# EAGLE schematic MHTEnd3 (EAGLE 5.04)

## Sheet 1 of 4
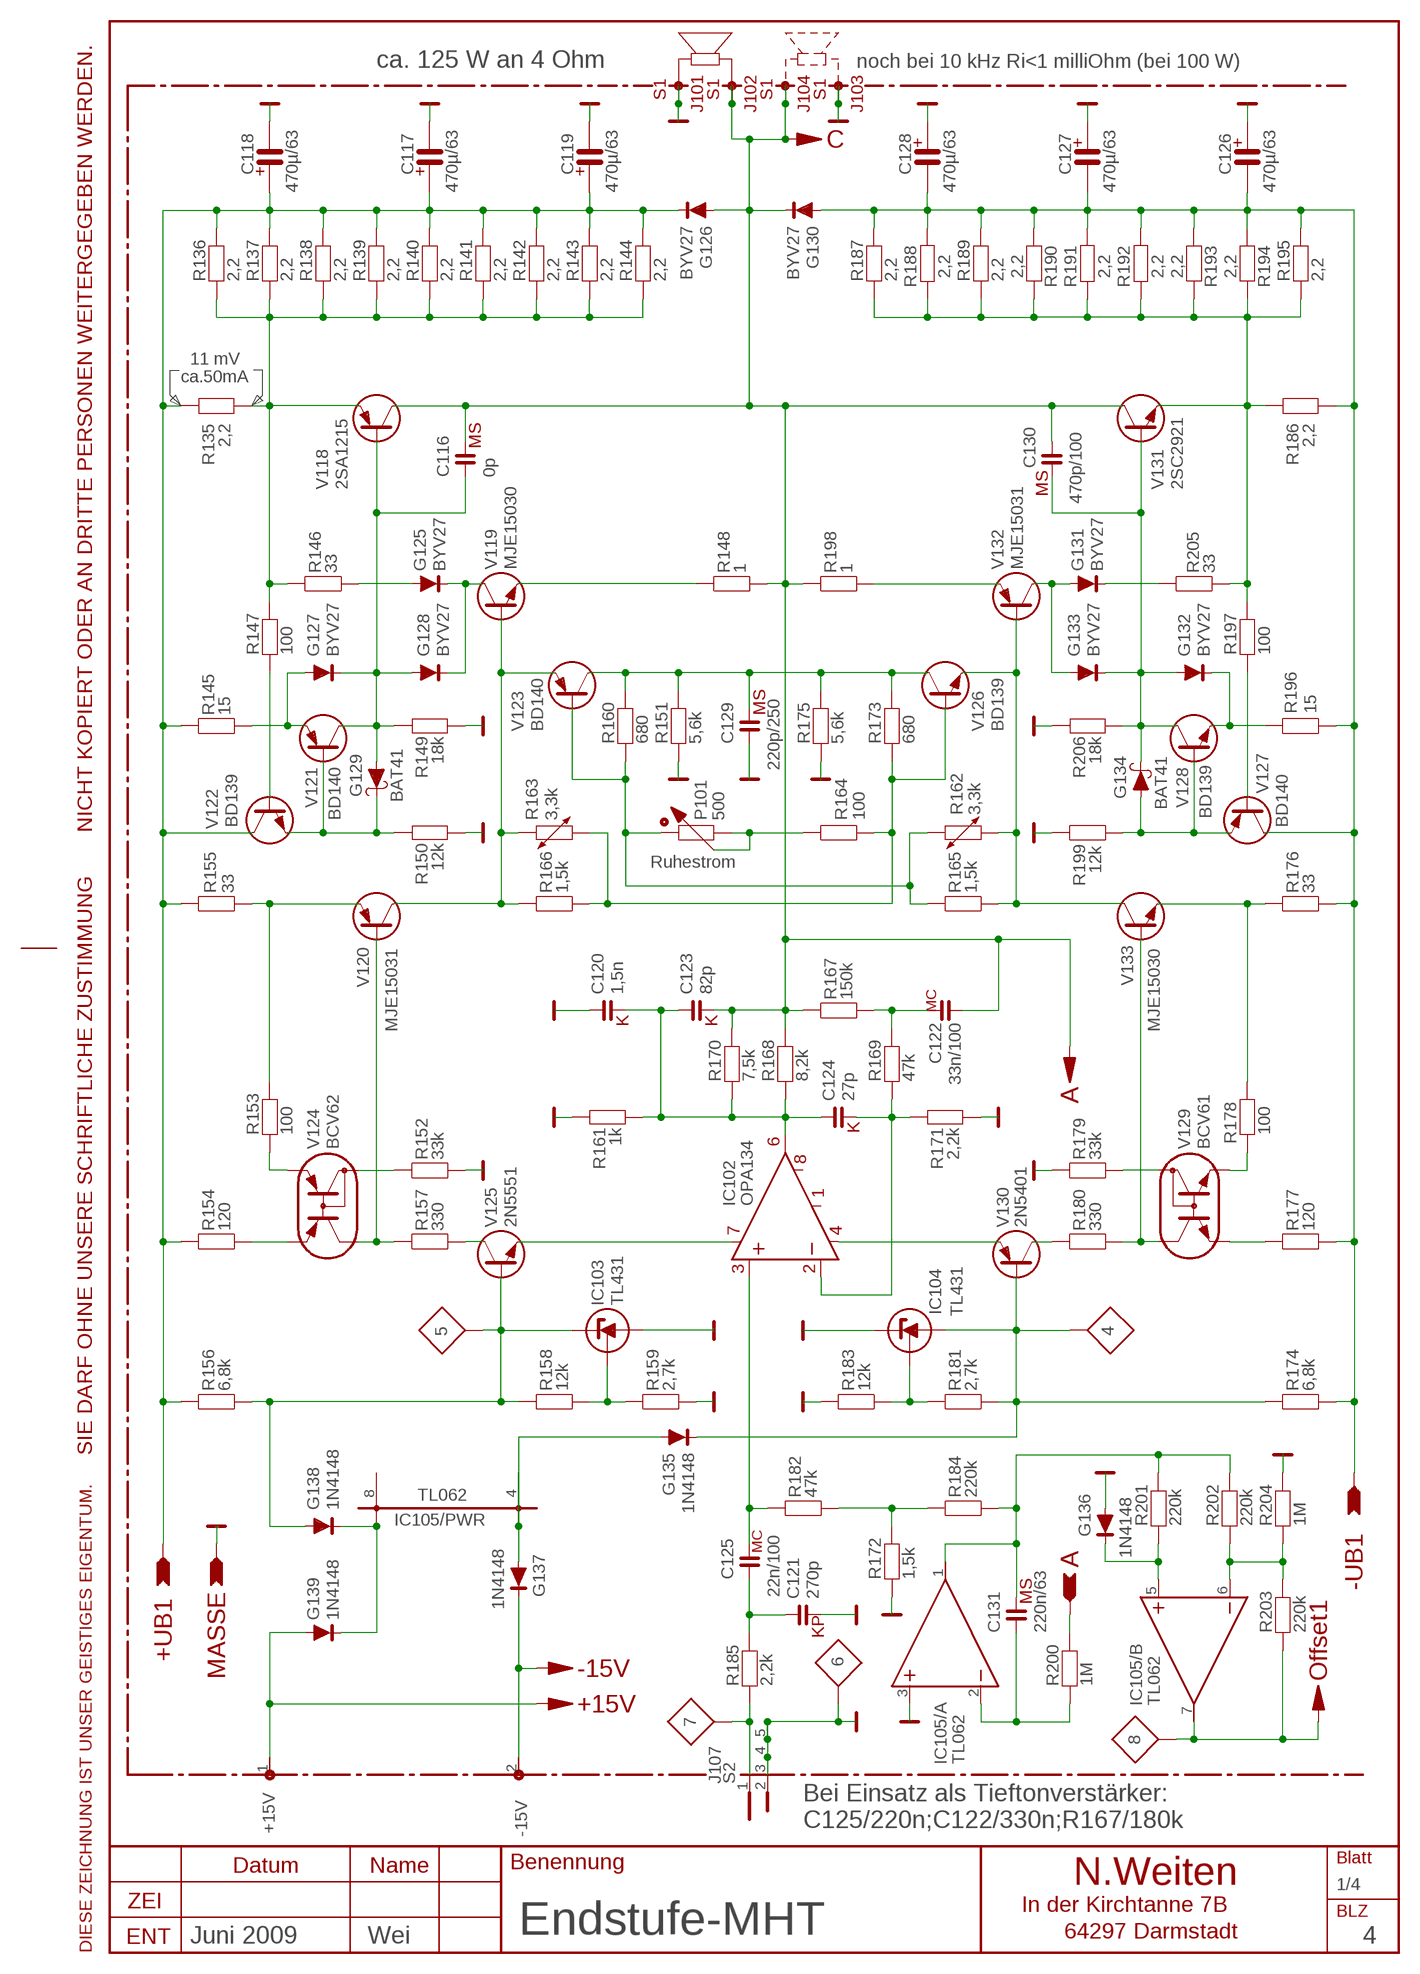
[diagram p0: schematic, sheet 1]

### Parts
C116  0p  M05S2,5/L  [M05T2,5]
C117  470µ/63  E05S12/LU  [E05S12,7U]
C118  470µ/63  E05S12/LU  [E05S12,7U]
C119  470µ/63  E05S12/LU  [E05S12,7U]
C120  1,5n  K5S  [K5]
C121  270p  KP5/7/S  [KP5/7]
C122  33n/100  M05C4,5/S  [M05T4,5]
C123  82p  K5S  [K5]
C124  27p  K5S  [K5]
C125  22n/100  M05C4,5/L  [M05T4,5]
C126  470µ/63  E05S12/LU  [E05S12,7U]
C127  470µ/63  E05S12/LU  [E05S12,7U]
C128  470µ/63  E05S12/LU  [E05S12,7U]
C129  220p/250  M05S4,5/L  [M05T4,5]
C130  470p/100  M05S2,5/L  [M05T2,5]
C131  220n/63  M05S2,5/L  [M05T2,5]
G125  BYV27  BYV27/S  [SOD-57]
G126  BYV27  BYV27/S  [SOD-57]
G127  BYV27  BYV27/S  [SOD-57]
G128  BYV27  BYV27/S  [SOD-57]
G129  BAT41  [DIO7-5]
G130  BYV27  BYV27/S  [SOD-57]
G131  BYV27  BYV27/S  [SOD-57]
G132  BYV27  BYV27/S  [SOD-57]
G133  BYV27  BYV27/S  [SOD-57]
G134  BAT41  [DIO7-5]
G135  1N4148  1N4148/S  [DIO7-5]
G136  1N4148  1N4148/L  [DIO7-5]
G137  1N4148  1N4148/L  [DIO7-5]
G138  1N4148  1N4148/S  [DIO7-5]
G139  1N4148  1N4148/S  [DIO7-5]
IC102  OPA134  LM6361N  [DIL-8]
IC103  TL431  [TO-92/BC]
IC104  TL431  [TO-92/BC]
IC105  TL062  LF353  [DIL-8]
J4  BERG02SW  [BERG02SW]
J101  FLACH6,3  [FLACH6,3]
J102  FLACH6,3  [FLACH6,3]
J103  FLACH6,3  [FLACH6,3]
J104  FLACH6,3  [FLACH6,3]
J107  SMB  SMBR665  [SMBR665]
MP7  7  MESS-R/S  [MESSPU/R]
MP11  5  MESS-R/S  [MESSPU/R]
MP12  4  MESS-R/S  [MESSPU/R]
MP13  6  MESS-R/L  [MESSPU/R]
MP15  8  MESS-R/S  [MESSPU/R]
P101  500  POT6,7/S  [T82P]
R135  2,2  R0207L7,5  [R7,5]
R136  2,2  R0207L7,5  [R7,5]
R137  2,2  R0207L7,5  [R7,5]
R138  2,2  R0207L7,5  [R7,5]
R139  2,2  R0207L7,5  [R7,5]
R140  2,2  R0207L7,5  [R7,5]
R141  2,2  R0207L7,5  [R7,5]
R142  2,2  R0207L7,5  [R7,5]
R143  2,2  R0207L7,5  [R7,5]
R144  2,2  R0207L7,5  [R7,5]
R145  15  R0207S7,5  [R7,5]
R146  33  R0207S7,5  [R7,5]
R147  100  R0204LR5  [R5]
R148  1  R0207S7,5  [R7,5]
R149  18k  R0207S7,5  [R7,5]
R150  12k  R0207S7,5  [R7,5]
R151  5,6k  R0207L7,5  [R7,5]
R152  33k  R0204SR5  [R5]
R153  100  R0204LR5  [R5]
R154  120  R0204SR5  [R5]
R155  33  R0204SR5  [R5]
R156  6,8k  R0207S7,5  [R7,5]
R157  330  R0204SR5  [R5]
R158  12k  R0204SR5  [R5]
R159  2,7k  R0204SR5  [R5]
R160  680  R0204LR5  [R5]
R161  1k  R0204SR5  [R5]
R162  3,3k  NTC5,0/SB  [NTC5,0B]
R163  3,3k  NTC5,0/SB  [NTC5,0B]
R164  100  R0204SR5  [R5]
R165  1,5k  R0204SR5  [R5]
R166  1,5k  R0204SR5  [R5]
R167  150k  R0204SR5  [R5]
R168  8,2k  R0204LR5  [R5]
R169  47k  R0204LR5  [R5]
R170  7,5k  R0204LR5  [R5]
R171  2,2k  R0204SR5  [R5]
R172  1,5k  R0204LR5  [R5]
R173  680  R0204LR5  [R5]
R174  6,8k  R0207S7,5  [R7,5]
R175  5,6k  R0207L7,5  [R7,5]
R176  33  R0204SR5  [R5]
R177  120  R0204SR5  [R5]
R178  100  R0204LR5  [R5]
R179  33k  R0204SR5  [R5]
R180  330  R0204SR5  [R5]
R181  2,7k  R0204SR5  [R5]
R182  47k  R0204SR5  [R5]
R183  12k  R0204SR5  [R5]
R184  220k  R0204SR5  [R5]
R185  2,2k  R0204LR5  [R5]
R186  2,2  R0207L7,5  [R7,5]
R187  2,2  R0207L7,5  [R7,5]
R188  2,2  R0207L7,5  [R7,5]
R189  2,2  R0207L7,5  [R7,5]
R190  2,2  R0207L7,5  [R7,5]
R191  2,2  R0207L7,5  [R7,5]
R192  2,2  R0207L7,5  [R7,5]
R193  2,2  R0207L7,5  [R7,5]
R194  2,2  R0207L7,5  [R7,5]
R195  2,2  R0207L7,5  [R7,5]
R196  15  R0207S7,5  [R7,5]
R197  100  R0204LR5  [R5]
R198  1  R0207S7,5  [R7,5]
R199  12k  R0207S7,5  [R7,5]
R200  1M  R0204LR5  [R5]
R201  220k  R0204LR5  [R5]
R202  220k  R0204LR5  [R5]
R203  220k  R0204LR5  [R5]
R204  1M  R0204LR5  [R5]
R205  33  R0207S7,5  [R7,5]
R206  18k  R0207S7,5  [R7,5]
V118  2SA1215  2SA1215SLU  [MT200LU]
V119  MJE15030  MJE15030LU  [TO-220/LU]
V120  MJE15031  MJE15031LU  [TO-220/LU]
V121  BD140  BD140S  [TO-126/S]
V122  BD139  BD139S  [TO-126/S]
V123  BD140  BD140LU  [TO-126/LU]
V124  BCV62  [SOT143]
V125  2N5551  [TO-92]
V126  BD139  BD139LU  [TO-126/LU]
V127  BD140  BD140S  [TO-126/S]
V128  BD139  BD139S  [TO-126/S]
V129  BCV61  [SOT143]
V130  2N5401  [TO-92]
V131  2SC2921  2SC2921SLU  [MT200LU]
V132  MJE15031  MJE15031LU  [TO-220/LU]
V133  MJE15030  MJE15030LU  [TO-220/LU]

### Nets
+UB1: C117.1 C118.1 C119.1 G126.2(K) R135.2 R136.2 R137.2 R138.2 R139.2 R140.2 R141.2 R142.2 R143.2 R144.2 R145.1 R154.1 R155.1 R156.1 V122.2(C) ; also sheet 3
-UB1: C126.2 C127.2 C128.2 G130.1(A) R174.2 R176.2 R177.2 R186.2 R187.2 R188.2 R189.2 R190.2 R191.2 R192.2 R193.2 R194.2 R195.2 R196.2 V127.2(C) ; also sheet 3
MASSE: C117.2 C118.2 C119.2 C120.1 C121.2 C126.1 C127.1 C128.1 C129.1 G136.1(A) IC103.2(A) IC104.3(K) IC105.3(/A:+IN) J101.1 J101.2 J103.1 J103.2 J107.2(MASSE) J107.3(MASSE) J107.4(MASSE) J107.5(MASSE) MP13.1 R149.2 R150.2 R151.1 R152.2 R159.2 R161.1 R171.2 R172.1 R175.1 R179.1 R183.1 R199.1 R204.2 R206.1 ; also sheet 2,3,4
N$1: C121.1 C125.1 R185.2
N$2: C125.2 IC102.3(+IN) R182.1
N$3: IC103.1(R) R158.2 R159.1
N$4: G138.1(A) IC103.3(K) MP11.1 R156.2 R158.1 V125.2(B)
N$5: IC102.7(V+) V125.1(E)
N$6: IC104.1(R) R181.1 R183.2
N$7: G135.2(K) IC104.2(A) MP12.1 R174.1 R181.2 V130.2(B)
N$8: IC102.4(V-) V130.1(E)
N$9: C120.2 C123.1 C124.1 IC102.6(OUT) R161.2 R168.1 R170.1
N$10: C124.2 IC102.2(-IN) R169.1 R171.1
N$11: C122.2 R167.2 R169.2
N$13: R157.2 V125.3(C)
N$14: R180.1 V130.3(C)
N$15: R153.2 R155.2 V120.3(E)
N$16: C129.2 R151.2 R160.2 R173.2 R175.2 V123.2(C) V126.2(C)
N$17: R154.2 V124.3(E1)
N$18: R162.2 R165.2 V126.1(E) V132.1(B) V133.2(C)
N$19: R157.1 V120.1(B) V124.2(C1)
N$20: R152.1 V124.1(B1B2C2)
N$21: R153.1 V124.4(E2)
N$22: R177.1 V129.3(E1)
N$23: C116.1 G127.2(K) G128.1(A) G129.1(A) R149.1 V118.1(B) V121.2(C)
N$24: G127.1(A) R145.2 V121.1(E)
N$25: J107.1 MP7.1 R185.1
N$26: R135.1 R136.1 R137.1 R138.1 R139.1 R140.1 R141.1 R142.1 R143.1 R144.1 R146.1 R147.2 V118.3(E)
N$27: R180.2 V129.2(C1) V133.1(B)
N$28: R179.2 V129.1(B1B2C2)
N$30: R178.1 V129.4(E2)
N$31: R176.1 R178.2 V133.3(E)
N$32: R147.1 V122.3(B)
N$33: G129.2(K) R150.1 V121.3(B) V122.1(E)
N$35: R186.1 R187.1 R188.1 R189.1 R190.1 R191.1 R192.1 R193.1 R194.1 R195.1 R197.2 R205.2 V131.3(E)
N$36: G132.2(K) R196.1 V128.1(E)
N$37: C130.2 G132.1(A) G133.2(K) G134.2(K) R206.2 V128.2(C) V131.1(B)
N$38: G131.1(A) G133.1(A) V132.2(C)
N$39: G131.2(K) R205.1
N$40: R197.1 V127.3(B)
N$41: G134.1(A) R199.2 V127.1(E) V128.3(B)
N$42: R148.1 V119.3(E)
N$43: C131.2 IC105.1(/A:OUT) R184.2 R201.2 R202.2
N$44: C131.1 IC105.2(/A:-IN) R200.1
N$45: G136.2(K) IC105.5(/B:+IN) R201.1
N$46: IC105.6(/B:-IN) R202.1 R203.2 R204.1
N$47: G135.1(A) G137.1(A) IC105.4(/PWR:VEE)
N$52: C116.2 C122.1 C123.2 C130.1 G126.1(A) G130.2(K) J102.1 J102.2 J104.1 J104.2 R148.2 R167.1 R168.2 R170.2 R198.1 R200.2 V118.2(C) V131.2(C) ; also sheet 3
N$93: R172.2 R182.2 R184.1
N$98: G137.2(K) J4.2 ; also sheet 2
N$187: R163.1 R166.1 V119.1(B) V120.2(C) V123.1(E)
N$204: P101.1 R160.1 R162.1 R165.1 V123.3(B)
N$205: R163.2 R164.2 R166.2 R173.1 V126.3(B)
N$214: G138.2(K) G139.2(K) IC105.8(/PWR:VCC)
N$215: G139.1(A) J4.1 ; also sheet 2
N$218: P101.2 P101.S R164.1
N$219: R198.2 V132.3(E)
N$220: G125.2(K) G128.2(K) V119.2(C)
N$221: G125.1(A) R146.2
OFFSET1: IC105.7(/B:OUT) MP15.1 R203.1 ; also sheet 3
Unconnected: IC102.1(BAL1) IC102.8(BAL2)

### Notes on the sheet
- ca. 125 W an 4 Ohm | noch bei 10 kHz Ri<1 milliOhm (bei 100 W)
- 11 mV
- ca.50mA
- Ruhestrom
- Bei Einsatz als Tieftonverstärker:
- C125/220n;C122/330n;R167/180k
- +15V | -15V
- Endstufe-MHT
- Juni 2009 | Wei | 4

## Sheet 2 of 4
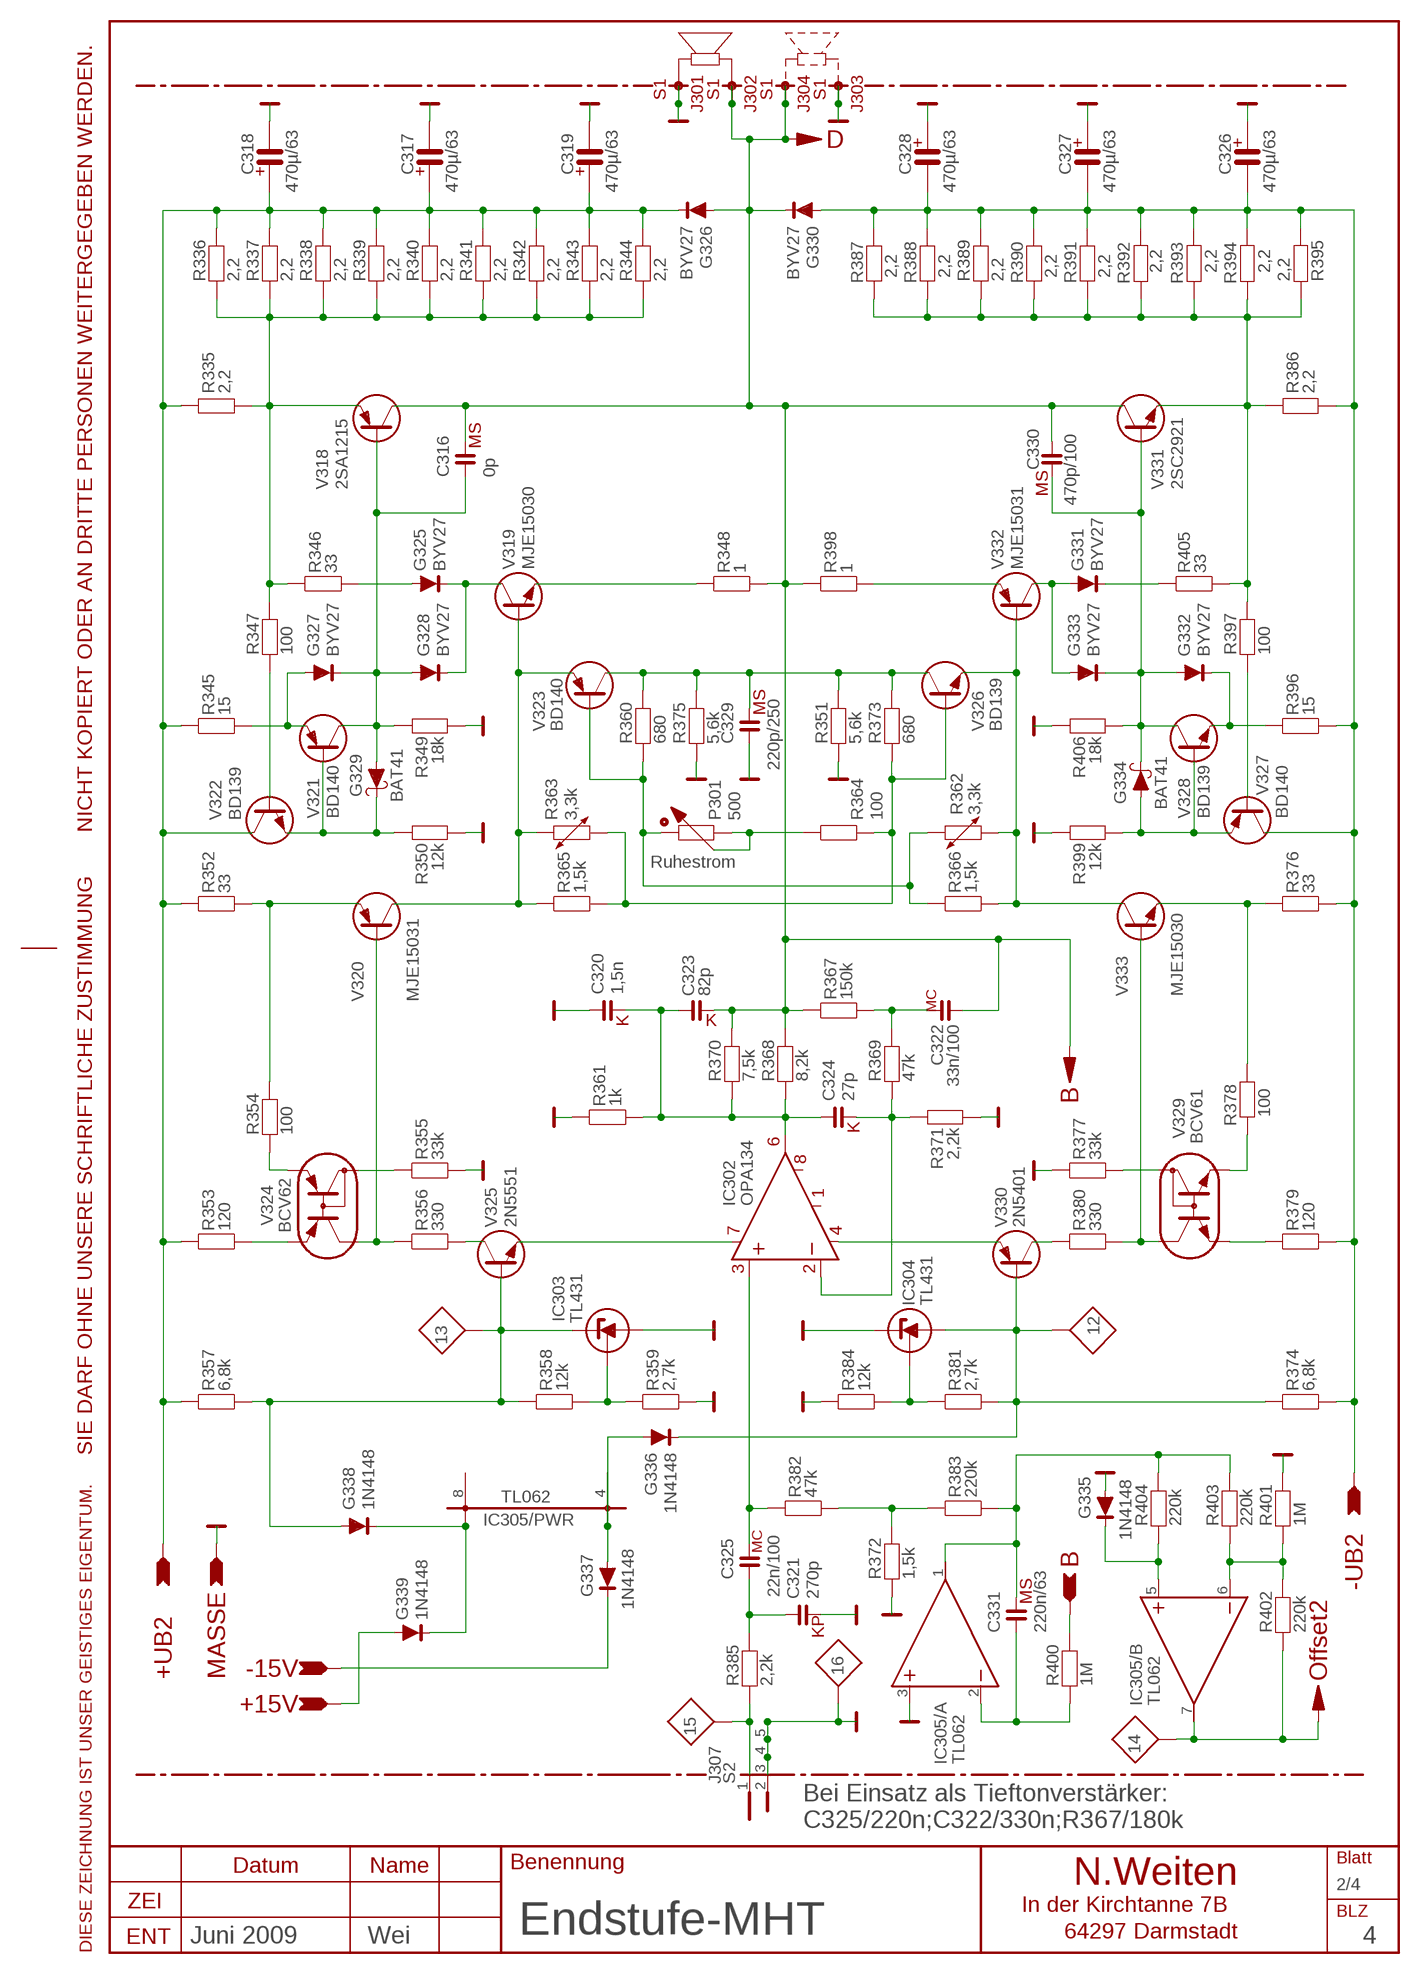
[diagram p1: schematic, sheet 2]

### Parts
C316  0p  M05S2,5/L  [M05T2,5]
C317  470µ/63  E05S12/LU  [E05S12,7U]
C318  470µ/63  E05S12/LU  [E05S12,7U]
C319  470µ/63  E05S12/LU  [E05S12,7U]
C320  1,5n  K5S  [K5]
C321  270p  KP5/7/S  [KP5/7]
C322  33n/100  M05C4,5/S  [M05T4,5]
C323  82p  K5L  [K5]
C324  27p  K5S  [K5]
C325  22n/100  M05C4,5/L  [M05T4,5]
C326  470µ/63  E05S12/LU  [E05S12,7U]
C327  470µ/63  E05S12/LU  [E05S12,7U]
C328  470µ/63  E05S12/LU  [E05S12,7U]
C329  220p/250  M05S4,5/L  [M05T4,5]
C330  470p/100  M05S2,5/L  [M05T2,5]
C331  220n/63  M05S2,5/L  [M05T2,5]
G325  BYV27  BYV27/S  [SOD-57]
G326  BYV27  BYV27/S  [SOD-57]
G327  BYV27  BYV27/S  [SOD-57]
G328  BYV27  BYV27/S  [SOD-57]
G329  BAT41  [DIO7-5]
G330  BYV27  BYV27/S  [SOD-57]
G331  BYV27  BYV27/S  [SOD-57]
G332  BYV27  BYV27/S  [SOD-57]
G333  BYV27  BYV27/S  [SOD-57]
G334  BAT41  [DIO7-5]
G335  1N4148  1N4148/L  [DIO7-5]
G336  1N4148  1N4148/S  [DIO7-5]
G337  1N4148  1N4148/L  [DIO7-5]
G338  1N4148  1N4148/S  [DIO7-5]
G339  1N4148  1N4148/S  [DIO7-5]
IC302  OPA134  LM6361N  [DIL-8]
IC303  TL431  [TO-92/BC]
IC304  TL431  [TO-92/BC]
IC305  TL062  LF353  [DIL-8]
J301  FLACH6,3  [FLACH6,3]
J302  FLACH6,3  [FLACH6,3]
J303  FLACH6,3  [FLACH6,3]
J304  FLACH6,3  [FLACH6,3]
J307  SMB  SMBR665  [SMBR665]
MP8  15  MESS-R/S  [MESSPU/R]
MP9  13  MESS-R/S  [MESSPU/R]
MP10  12  MESS-R/S  [MESSPU/R]
MP14  16  MESS-R/L  [MESSPU/R]
MP16  14  MESS-R/S  [MESSPU/R]
P301  500  POT6,7/S  [T82P]
R335  2,2  R0207L7,5  [R7,5]
R336  2,2  R0207L7,5  [R7,5]
R337  2,2  R0207L7,5  [R7,5]
R338  2,2  R0207L7,5  [R7,5]
R339  2,2  R0207L7,5  [R7,5]
R340  2,2  R0207L7,5  [R7,5]
R341  2,2  R0207L7,5  [R7,5]
R342  2,2  R0207L7,5  [R7,5]
R343  2,2  R0207L7,5  [R7,5]
R344  2,2  R0207L7,5  [R7,5]
R345  15  R0207S7,5  [R7,5]
R346  33  R0207S7,5  [R7,5]
R347  100  R0204LR5  [R5]
R348  1  R0207S7,5  [R7,5]
R349  18k  R0207S7,5  [R7,5]
R350  12k  R0207S7,5  [R7,5]
R351  5,6k  R0207L7,5  [R7,5]
R352  33  R0204SR5  [R5]
R353  120  R0204SR5  [R5]
R354  100  R0204LR5  [R5]
R355  33k  R0204SR5  [R5]
R356  330  R0204SR5  [R5]
R357  6,8k  R0207S7,5  [R7,5]
R358  12k  R0204SR5  [R5]
R359  2,7k  R0204SR5  [R5]
R360  680  R0204LR5  [R5]
R361  1k  R0204SR5  [R5]
R362  3,3k  NTC5,0/SB  [NTC5,0B]
R363  3,3k  NTC5,0/SB  [NTC5,0B]
R364  100  R0204SR5  [R5]
R365  1,5k  R0204SR5  [R5]
R366  1,5k  R0204SR5  [R5]
R367  150k  R0204SR5  [R5]
R368  8,2k  R0204LR5  [R5]
R369  47k  R0204LR5  [R5]
R370  7,5k  R0204LR5  [R5]
R371  2,2k  R0204SR5  [R5]
R372  1,5k  R0204LR5  [R5]
R373  680  R0204LR5  [R5]
R374  6,8k  R0207S7,5  [R7,5]
R375  5,6k  R0207L7,5  [R7,5]
R376  33  R0204SR5  [R5]
R377  33k  R0204SR5  [R5]
R378  100  R0204LR5  [R5]
R379  120  R0204SR5  [R5]
R380  330  R0204SR5  [R5]
R381  2,7k  R0204SR5  [R5]
R382  47k  R0204SR5  [R5]
R383  220k  R0204SR5  [R5]
R384  12k  R0204SR5  [R5]
R385  2,2k  R0204LR5  [R5]
R386  2,2  R0207L7,5  [R7,5]
R387  2,2  R0207L7,5  [R7,5]
R388  2,2  R0207L7,5  [R7,5]
R389  2,2  R0207L7,5  [R7,5]
R390  2,2  R0207L7,5  [R7,5]
R391  2,2  R0207L7,5  [R7,5]
R392  2,2  R0207L7,5  [R7,5]
R393  2,2  R0207L7,5  [R7,5]
R394  2,2  R0207L7,5  [R7,5]
R395  2,2  R0207L7,5  [R7,5]
R396  15  R0207S7,5  [R7,5]
R397  100  R0204LR5  [R5]
R398  1  R0207S7,5  [R7,5]
R399  12k  R0207S7,5  [R7,5]
R400  1M  R0204LR5  [R5]
R401  1M  R0204LR5  [R5]
R402  220k  R0204LR5  [R5]
R403  220k  R0204LR5  [R5]
R404  220k  R0204LR5  [R5]
R405  33  R0207S7,5  [R7,5]
R406  18k  R0207S7,5  [R7,5]
V318  2SA1215  2SA1215SLU  [MT200LU]
V319  MJE15030  MJE15030LU  [TO-220/LU]
V320  MJE15031  MJE15031LU  [TO-220/LU]
V321  BD140  BD140S  [TO-126/S]
V322  BD139  BD139S  [TO-126/S]
V323  BD140  BD140LU  [TO-126/LU]
V324  BCV62  [SOT143]
V325  2N5551  [TO-92]
V326  BD139  BD139LU  [TO-126/LU]
V327  BD140  BD140S  [TO-126/S]
V328  BD139  BD139S  [TO-126/S]
V329  BCV61  [SOT143]
V330  2N5401  [TO-92]
V331  2SC2921  2SC2921SLU  [MT200LU]
V332  MJE15031  MJE15031LU  [TO-220/LU]
V333  MJE15030  MJE15030LU  [TO-220/LU]

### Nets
+UB2: C317.1 C318.1 C319.1 G326.2(K) R335.2 R336.2 R337.2 R338.2 R339.2 R340.2 R341.2 R342.2 R343.2 R344.2 R345.1 R352.1 R353.1 R357.1 V322.2(C) ; also sheet 4
-UB2: C326.2 C327.2 C328.2 G330.1(A) R374.2 R376.2 R379.2 R386.2 R387.2 R388.2 R389.2 R390.2 R391.2 R392.2 R393.2 R394.2 R395.2 R396.2 V327.2(C) ; also sheet 4
MASSE: C317.2 C318.2 C319.2 C320.1 C321.2 C326.1 C327.1 C328.1 C329.1 G335.1(A) IC303.2(A) IC304.3(K) IC305.3(/A:+IN) J301.1 J301.2 J303.1 J303.2 J307.2(MASSE) J307.3(MASSE) J307.4(MASSE) J307.5(MASSE) MP14.1 R349.2 R350.2 R351.1 R355.2 R359.2 R361.1 R371.2 R372.1 R375.1 R377.1 R384.1 R399.1 R401.2 R406.1 ; also sheet 1,3,4
N$54: C325.2 IC302.3(+IN) R382.1
N$55: IC303.1(R) R358.2 R359.1
N$56: G338.1(A) IC303.3(K) MP9.1 R357.2 R358.1 V325.2(B)
N$58: IC304.1(R) R381.1 R384.2
N$59: IC302.4(V-) V330.1(E)
N$60: C320.2 C323.1 C324.1 IC302.6(OUT) R361.2 R368.1 R370.1
N$61: C324.2 IC302.2(-IN) R369.1 R371.1
N$62: C322.2 R367.2 R369.2
N$63: R356.2 V325.3(C)
N$64: R380.1 V330.3(C)
N$65: R352.2 R354.2 V320.3(E)
N$66: R363.1 R365.1 V319.1(B) V320.2(C) V323.1(E)
N$67: R353.2 V324.3(E1)
N$68: R356.1 V320.1(B) V324.2(C1)
N$69: R355.1 V324.1(B1B2C2)
N$70: R354.1 V324.4(E2)
N$72: IC302.7(V+) V325.1(E)
N$73: G327.1(A) R345.2 V321.1(E)
N$74: R335.1 R336.1 R337.1 R338.1 R339.1 R340.1 R341.1 R342.1 R343.1 R344.1 R346.1 R347.2 V318.3(E)
N$75: R380.2 V329.2(C1) V333.1(B)
N$76: R377.2 V329.1(B1B2C2)
N$77: R379.1 V329.3(E1)
N$78: R378.1 V329.4(E2)
N$79: R376.1 R378.2 V333.3(E)
N$80: R362.2 R366.2 V326.1(E) V332.1(B) V333.2(C)
N$82: R386.1 R387.1 R388.1 R389.1 R390.1 R391.1 R392.1 R393.1 R394.1 R395.1 R397.2 R405.2 V331.3(E)
N$83: G332.2(K) R396.1 V328.1(E)
N$84: C330.2 G332.1(A) G333.2(K) G334.2(K) R406.2 V328.2(C) V331.1(B)
N$85: J307.1 MP8.1 R385.1
N$86: R347.1 V322.3(B)
N$87: P301.1 R360.1 R362.1 R366.1 V323.3(B)
N$88: R363.2 R364.2 R365.2 R373.1 V326.3(B)
N$89: G336.2(K) IC304.2(A) MP10.1 R374.1 R381.2 V330.2(B)
N$90: C329.2 R351.2 R360.2 R373.2 R375.2 V323.2(C) V326.2(C)
N$91: G329.2(K) R350.1 V321.3(B) V322.1(E)
N$92: G325.1(A) R346.2
N$94: C331.2 IC305.1(/A:OUT) R383.2 R403.2 R404.2
N$95: C331.1 IC305.2(/A:-IN) R400.1
N$96: G335.2(K) IC305.5(/B:+IN) R404.1
N$97: IC305.6(/B:-IN) R401.1 R402.2 R403.1
N$98: G337.2(K) ; also sheet 1
N$103: C316.2 C322.1 C323.2 C330.1 G326.1(A) G330.2(K) J302.1 J302.2 J304.1 J304.2 R348.2 R367.1 R368.2 R370.2 R398.1 R400.2 V318.2(C) V331.2(C) ; also sheet 4
N$107: C316.1 G327.2(K) G328.1(A) G329.1(A) R349.1 V318.1(B) V321.2(C)
N$108: C321.1 C325.1 R385.2
N$155: G336.1(A) G337.1(A) IC305.4(/PWR:VEE)
N$179: P301.2 P301.S R364.1
N$181: G325.2(K) G328.2(K) V319.2(C)
N$185: R372.2 R382.2 R383.1
N$215: G339.1(A) ; also sheet 1
N$216: G338.2(K) G339.2(K) IC305.8(/PWR:VCC)
N$224: R348.1 V319.3(E)
N$225: G331.2(K) R405.1
N$226: G331.1(A) G333.1(A) V332.2(C)
N$227: R397.1 V327.3(B)
N$228: G334.1(A) R399.2 V327.1(E) V328.3(B)
N$229: R398.2 V332.3(E)
OFFSET2: IC305.7(/B:OUT) MP16.1 R402.1 ; also sheet 4
Unconnected: IC302.1(BAL1) IC302.8(BAL2)

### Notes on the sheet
- Ruhestrom
- Bei Einsatz als Tieftonverstärker:
- C325/220n;C322/330n;R367/180k
- Endstufe-MHT
- Juni 2009 | Wei | 4

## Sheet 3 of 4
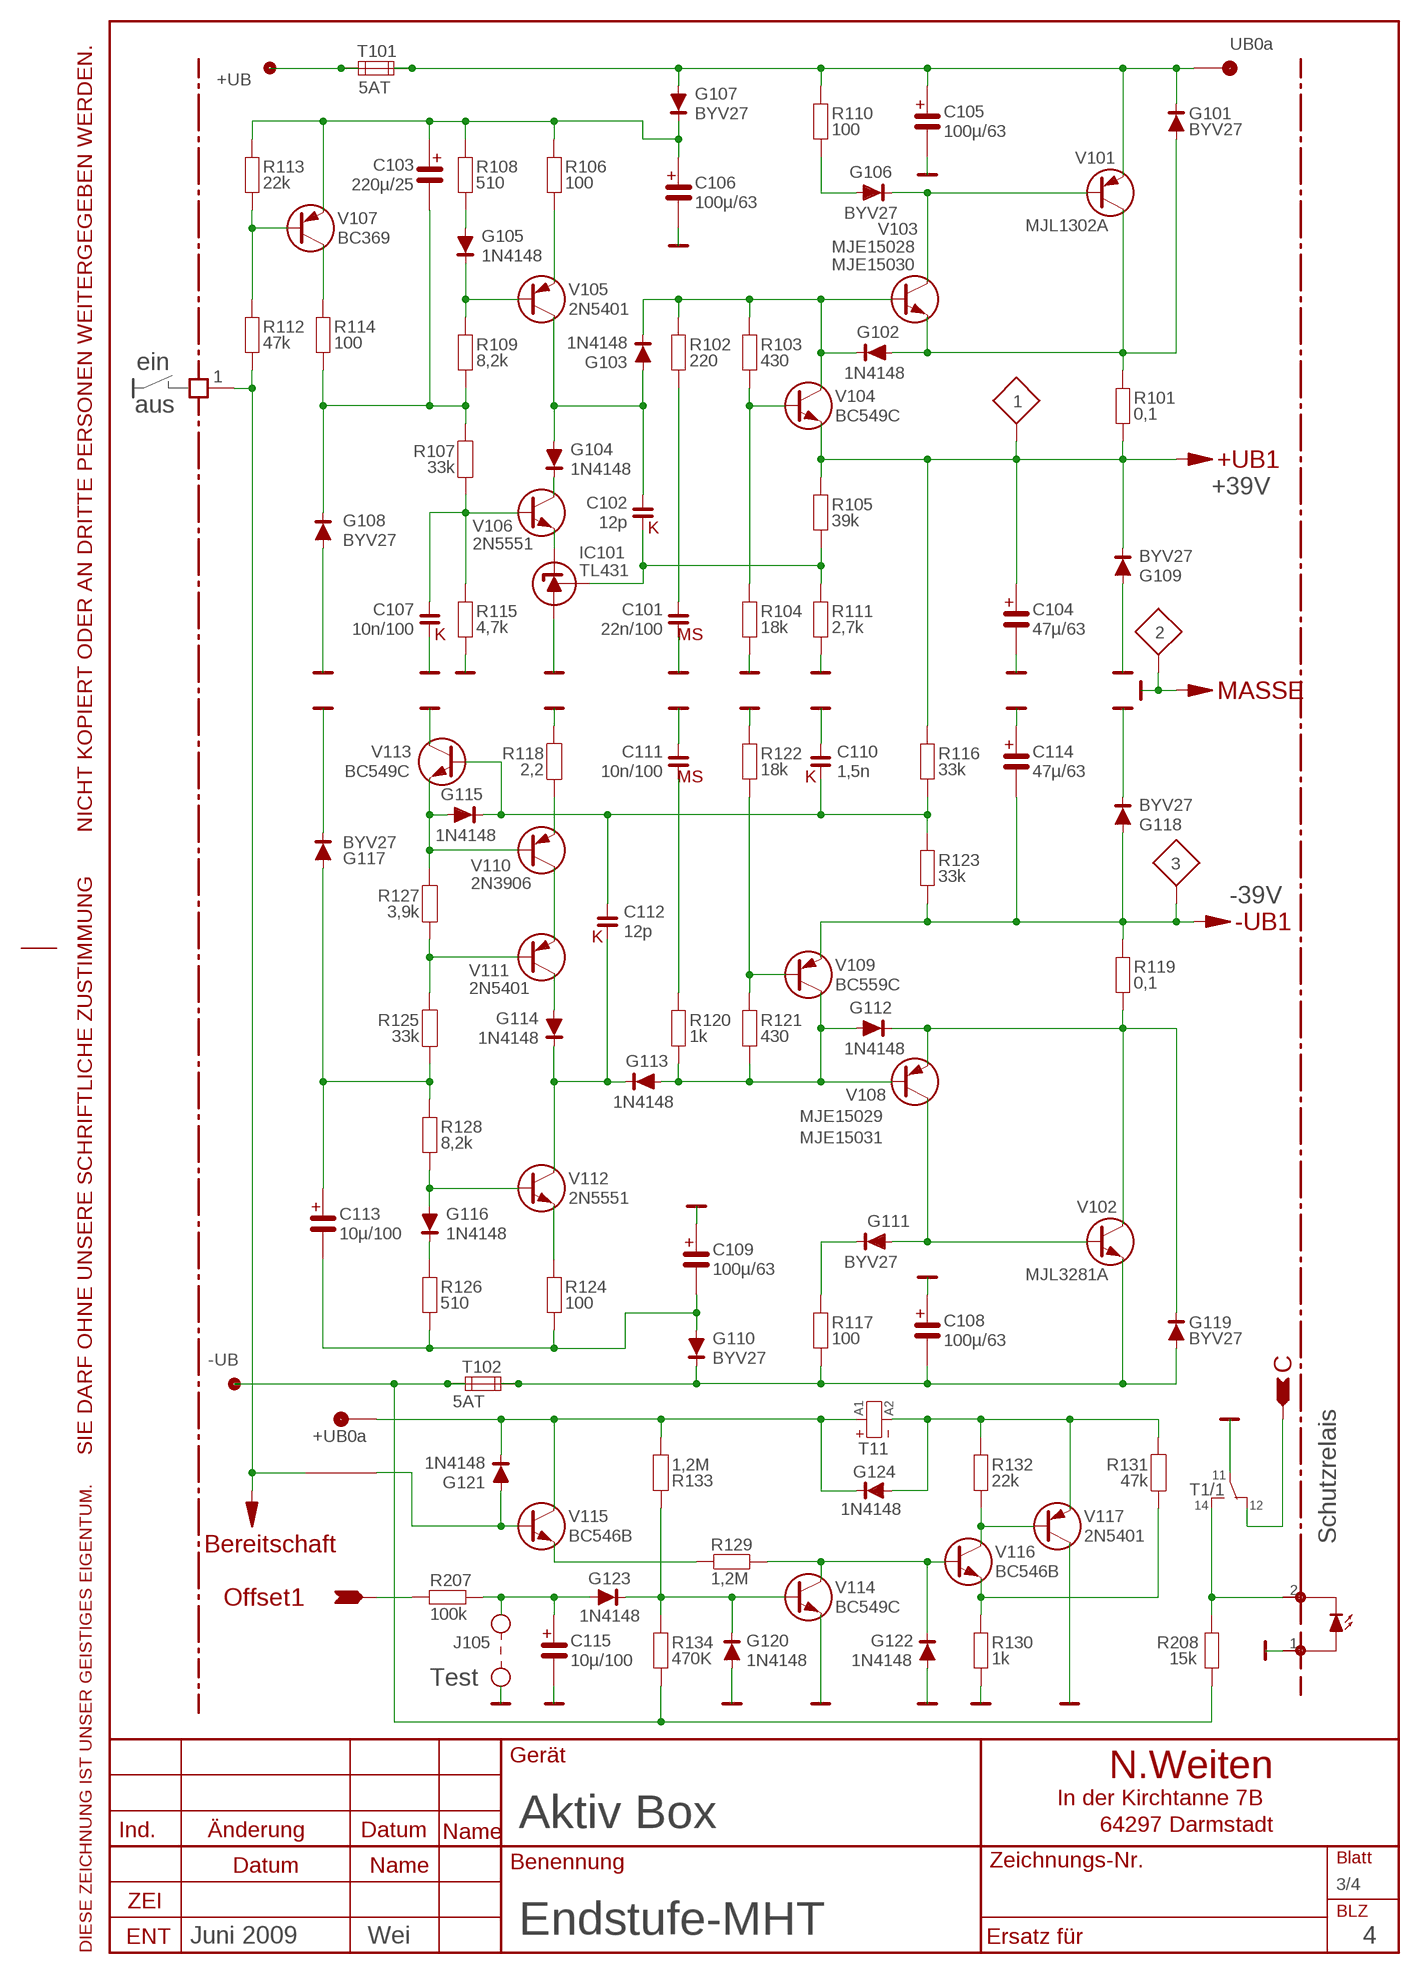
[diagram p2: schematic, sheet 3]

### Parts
C101  22n/100  M05S2,5/S  [M05T2,5]
C102  12p  K5S  [K5]
C103  220µ/25  E3,5S08/S  [E3,5S08]
C104  47µ/63  E3,5S08/S  [E3,5S08]
C105  100µ/63  E05S10/S  [E05S10,5]
C106  100µ/63  E05S10/S  [E05S10,5]
C107  10n/100  K5S  [K5]
C108  100µ/63  E05S10/S  [E05S10,5]
C109  100µ/63  E05S10/S  [E05S10,5]
C110  1,5n  K5S  [K5]
C111  10n/100  M05S2,5/S  [M05T2,5]
C112  12p  K5S  [K5]
C113  10µ/100  E2,0S05/S  [E2,0S05]
C114  47µ/63  E2,5S08/S  [E2,5S08]
C115  10µ/100  E2,0S05/S  [E2,0S05]
G101  BYV27  BYV27/S  [SOD-57]
G102  1N4148  1N4148/L  [DIO7-5]
G103  1N4148  1N4148/S  [DIO7-5]
G104  1N4148  1N4148/S  [DIO7-5]
G105  1N4148  1N4148/S  [DIO7-5]
G106  BYV27  BYV27/L  [SOD-57]
G107  BYV27  BYV27/S  [SOD-57]
G108  BYV27  BYV27/S  [SOD-57]
G109  BYV27  BYV27/S  [SOD-57]
G110  BYV27  BYV27/S  [SOD-57]
G111  BYV27  BYV27/L  [SOD-57]
G112  1N4148  1N4148/L  [DIO7-5]
G113  1N4148  1N4148/L  [DIO7-5]
G114  1N4148  1N4148/S  [DIO7-5]
G115  1N4148  1N4148/L  [DIO7-5]
G116  1N4148  1N4148/S  [DIO7-5]
G117  BYV27  BYV27/S  [SOD-57]
G118  BYV27  BYV27/S  [SOD-57]
G119  BYV27  BYV27/S  [SOD-57]
G120  1N4148  1N4148/S  [DIO7-5]
G121  1N4148  1N4148/S  [DIO7-5]
G122  1N4148  1N4148/S  [DIO7-5]
G123  1N4148  1N4148/S  [DIO7-5]
G124  1N4148  1N4148/S  [DIO7-5]
IC101  TL431  [TO-92/BC]
J105  BERG02SG  JUMP/O/S  [BERG02SG]
J106  BERG02SW  [BERG02SW]
MP1  1  MESS-R/S  [MESSPU/R]
MP2  3  MESS-R/S  [MESSPU/R]
MP3  2  MESS-R/S  [MESSPU/R]
R101  0,1  R25X6,5/S  [R27,5]
R102  220  R0204SR5  [R5]
R103  430  R0204SR5  [R5]
R104  18k  R0204SR5  [R5]
R105  39k  R0204SR5  [R5]
R106  100  R0204SR5  [R5]
R107  33k  R0204SR5  [R5]
R108  510  R0204SR5  [R5]
R109  8,2k  R0204SR5  [R5]
R110  100  R0207S7,5  [R7,5]
R111  2,7k  R0204SR5  [R5]
R112  47k  R0204SR5  [R5]
R113  22k  R0204SR5  [R5]
R114  100  R0204SR5  [R5]
R115  4,7k  R0204SR5  [R5]
R116  33k  R0207S7,5  [R7,5]
R117  100  R0207S7,5  [R7,5]
R118  2,2  R0204SR5  [R5]
R119  0,1  R25X6,5/S  [R27,5]
R120  1k  R0204SR5  [R5]
R121  430  R0204SR5  [R5]
R122  18k  R0204SR5  [R5]
R123  33k  R0204SR5  [R5]
R124  100  R0204SR5  [R5]
R125  33k  R0204SR5  [R5]
R126  510  R0204SR5  [R5]
R127  3,9k  R0204SR5  [R5]
R128  8,2k  R0204SR5  [R5]
R129  1,2M  R0204SR5  [R5]
R130  1k  R0204SR5  [R5]
R131  47k  R0204SR5  [R5]
R132  22k  R0204SR5  [R5]
R133  1,2M  R0204LR5  [R5]
R134  470K  R0204SR5  [R5]
R207  100k  R0204LR5  [R5]
R208  15k  R0207S7,5  [R7,5]
T1  TYCORT314  [TYCORT314]
T101  5AT  SI520/L  [SICH5*20]
T102  5AT  SI520/L  [SICH5*20]
U$200  1  LÖTFA  [LÖTFA]
V101  MJL1302A  MJL1302ALU  [TO-264/LU]
V102  MJL3281A  MJL3281ALU  [TO-264/LU]
V103  MJE15028  MJE15030LU  [TO-220/LU]
V104  BC549C  [TO-92/BC]
V105  2N5401  [TO-92]
V106  2N5551  [TO-92]
V107  BC369  BC640  [SOT-54]
V108  MJE15029  MJE15031LU  [TO-220/LU]
V109  BC559C  [TO-92/BC]
V110  2N3906  [TO-92]
V111  2N5401  [TO-92]
V112  2N5551  [TO-92]
V113  BC549C  [TO-92/BC]
V114  BC549C  [TO-92/BC]
V115  BC546B  BC547C  [TO-92/BC]
V116  BC546B  BC547C  [TO-92/BC]
V117  2N5401  [TO-92]

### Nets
+UB: T101.1 T101.2 ; also sheet 4
+UB1: C104.1 G109.2(K) MP1.1 R101.2 R105.1 R116.1 V104.3(E) ; also sheet 1
-UB: R134.2 R208.1 T102.1 T102.2 ; also sheet 4
-UB0: C108.2 G110.2(K) G119.1(A) R117.2 T102.3 T102.4 V102.3(E)
-UB1: C114.2 G118.1(A) MP2.1 R119.1 R123.2 V109.3(E) ; also sheet 1
MASSE: C101.2 C104.2 C105.2 C106.2 C107.2 C108.1 C109.1 C110.1 C111.1 C114.1 C115.2 G108.1(A) G109.1(A) G117.2(K) G118.2(K) G120.1(A) G122.1(A) IC101.2(A) J105.2 J106.1 MP3.1 R104.2 R111.2 R115.2 R118.1 R122.1 R130.2 T1.11 V113.1(C) V114.3(E) V117.3(C) ; also sheet 1,2,4
N$52: T1.12 ; also sheet 1
N$57: R132.2 V116.1(C) V117.2(B)
N$81: R130.1 R131.2 V116.3(E)
N$100: C105.1 G101.2(K) G107.1(A) R110.1 T101.3 T101.4 V101.3(E)
N$104: C115.1 G123.1(A) J105.1 R207.2
N$142: G121.2(K) G124.2(K) R133.2 T1.A1(1:A1) V115.1(C)
N$143: G105.1(A) R108.2
N$144: G105.2(K) R109.1 V105.2(B)
N$145: R106.2 V105.1(E)
N$146: C103.2 G108.2(K) R107.1 R109.2 R114.2
N$147: C107.1 R107.2 R115.1 V106.2(B)
N$148: G102.2(K) G103.2(K) R102.1 R103.1 V103.1(B) V104.1(C)
N$149: IC101.3(K) V106.1(E)
N$150: G106.2(K) V101.1(B) V103.2(C)
N$151: G101.1(A) G102.1(A) R101.1 V101.2(C) V103.3(E)
N$152: R103.2 R104.1 V104.2(B)
N$154: C102.2 IC101.1(R) R105.2 R111.1
N$157: R118.2 V110.1(E)
N$158: G115.1(A) R127.1 V110.2(B) V113.3(E)
N$159: V110.3(C) V111.1(E)
N$160: R125.1 R127.2 V111.2(B)
N$161: C110.2 C112.1 G115.2(K) R116.2 R123.1 V113.2(B)
N$162: R121.1 R122.2 V109.2(B)
N$163: G112.1(A) G113.1(A) R120.2 R121.2 V108.1(B) V109.1(C)
N$164: G112.2(K) G119.2(K) R119.2 V102.2(C) V108.3(E)
N$165: G111.1(A) V102.1(B) V108.2(C)
N$166: R124.1 V112.1(E)
N$167: G116.2(K) R126.1
N$168: G116.1(A) R128.2 V112.2(B)
N$169: C113.1 G117.1(A) R125.2 R128.1
N$170: C101.1 R102.2
N$171: C111.2 R120.1
N$172: C103.1 C106.1 G107.2(K) R106.1 R108.1 R113.1 V107.E
N$173: C109.2 C113.2 G110.1(A) R124.2 R126.2
N$174: G104.2(K) V106.3(C)
N$175: R114.1 V107.C
N$176: R112.1 R113.2 V107.B
N$177: R112.2 U$200.1 ; also sheet 4
N$178: G114.1(A) V111.3(C)
N$184: G120.2(K) G123.2(K) R133.1 R134.1 V114.2(B)
N$188: J106.2 R208.2 T1.14
N$189: R129.1 V115.3(E)
N$190: G124.1(A) R131.1 R132.1 T1.A2(1:A2) V117.1(E)
N$202: G111.2(K) R117.1
N$203: G106.1(A) R110.2
N$209: G122.2(K) R129.2 V114.1(C) V116.2(B)
N$211: G121.1(A) V115.2(B) ; also sheet 4
N$222: C102.1 G103.1(A) G104.1(A) V105.3(C)
N$223: C112.2 G113.2(K) G114.2(K) V112.3(C)
OFFSET1: R207.1 ; also sheet 1

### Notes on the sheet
- UB0a
- MJE15030
- ein
- aus
- +39V
- -39V
- MJE15031
- +UB0a
- Schutzrelais
- Test
- Aktiv Box
- Endstufe-MHT
- Juni 2009 | Wei | 4

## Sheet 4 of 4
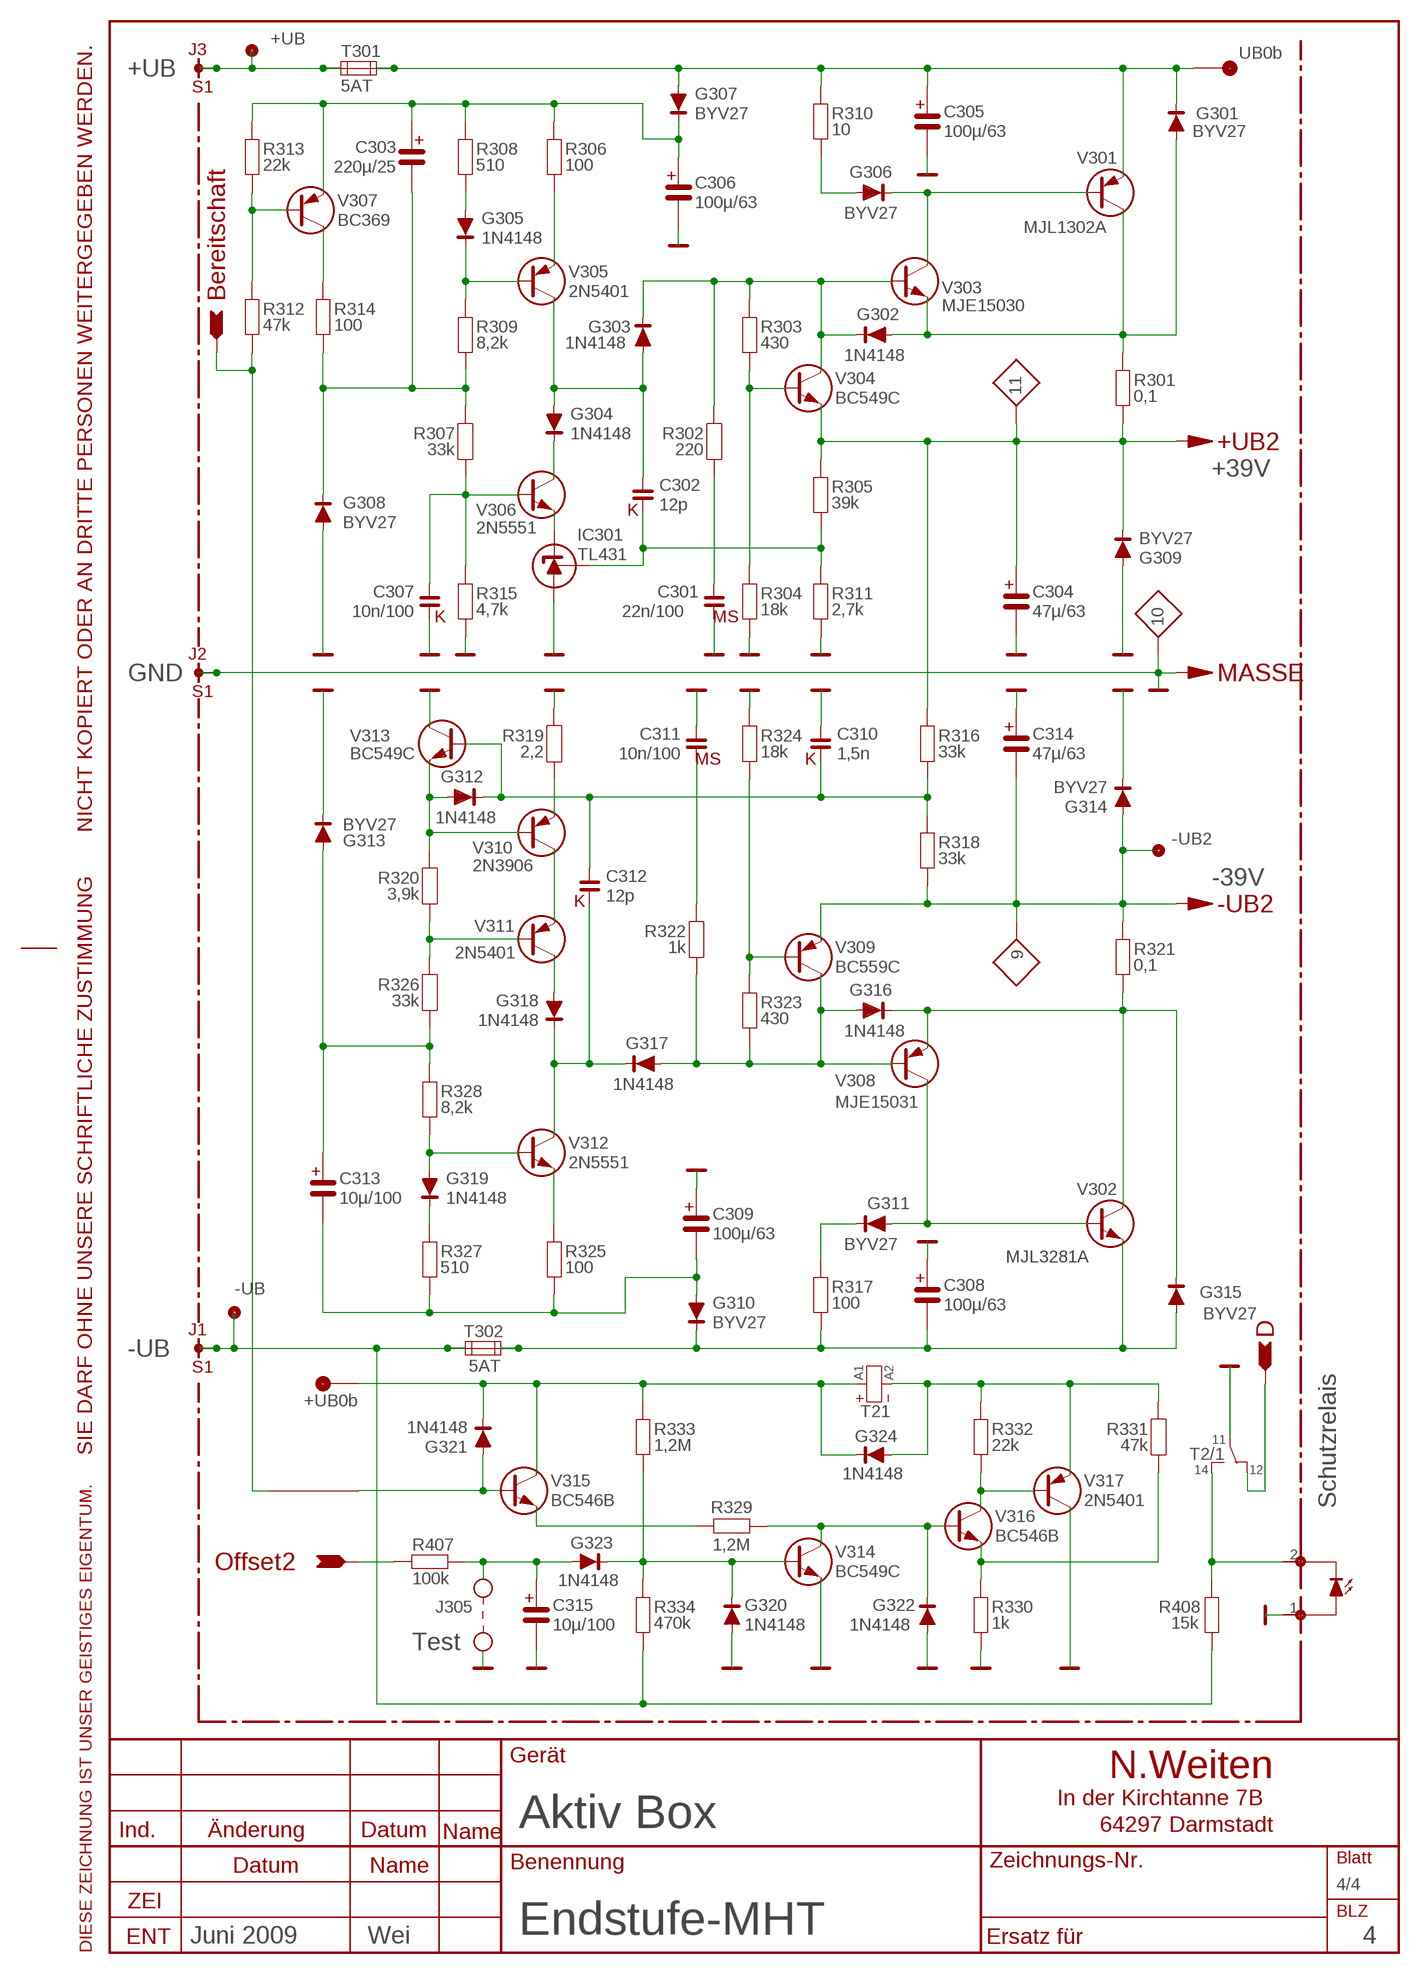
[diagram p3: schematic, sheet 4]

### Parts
C301  22n/100  M05S2,5/S  [M05T2,5]
C302  12p  K5S  [K5]
C303  220µ/25  E3,5S08/S  [E3,5S08]
C304  47µ/63  E3,5S08/S  [E3,5S08]
C305  100µ/63  E05S10/S  [E05S10,5]
C306  100µ/63  E05S10/S  [E05S10,5]
C307  10n/100  K5S  [K5]
C308  100µ/63  E05S10/S  [E05S10,5]
C309  100µ/63  E05S10/S  [E05S10,5]
C310  1,5n  K5S  [K5]
C311  10n/100  M05S2,5/S  [M05T2,5]
C312  12p  K5S  [K5]
C313  10µ/100  E2,0S05/S  [E2,0S05]
C314  47µ/63  E2,5S08/S  [E2,5S08]
C315  10µ/100  E2,0S05/S  [E2,0S05]
G301  BYV27  BYV27/S  [SOD-57]
G302  1N4148  1N4148/L  [DIO7-5]
G303  1N4148  1N4148/L  [DIO7-5]
G304  1N4148  1N4148/S  [DIO7-5]
G305  1N4148  1N4148/S  [DIO7-5]
G306  BYV27  BYV27/L  [SOD-57]
G307  BYV27  BYV27/S  [SOD-57]
G308  BYV27  BYV27/S  [SOD-57]
G309  BYV27  BYV27/S  [SOD-57]
G310  BYV27  BYV27/S  [SOD-57]
G311  BYV27  BYV27/L  [SOD-57]
G312  1N4148  1N4148/L  [DIO7-5]
G313  BYV27  BYV27/S  [SOD-57]
G314  BYV27  BYV27/S  [SOD-57]
G315  BYV27  BYV27/S  [SOD-57]
G316  1N4148  1N4148/L  [DIO7-5]
G317  1N4148  1N4148/L  [DIO7-5]
G318  1N4148  1N4148/S  [DIO7-5]
G319  1N4148  1N4148/S  [DIO7-5]
G320  1N4148  1N4148/S  [DIO7-5]
G321  1N4148  1N4148/S  [DIO7-5]
G322  1N4148  1N4148/S  [DIO7-5]
G323  1N4148  1N4148/S  [DIO7-5]
G324  1N4148  1N4148/S  [DIO7-5]
IC301  TL431  [TO-92/BC]
J1  FLACH6,3  [FLACH6,3]
J2  FLACH6,3  [FLACH6,3]
J3  FLACH6,3  [FLACH6,3]
J305  BERG02SG  JUMP/O/S  [BERG02SG]
J306  BERG02SW  [BERG02SW]
MP4  9  MESS-R/L  [MESSPU/R]
MP5  10  MESS-R/L  [MESSPU/R]
MP6  11  MESS-R/L  [MESSPU/R]
R301  0,1  R25X6,5/S  [R27,5]
R302  220  R0204SR5  [R5]
R303  430  R0204SR5  [R5]
R304  18k  R0204SR5  [R5]
R305  39k  R0204SR5  [R5]
R306  100  R0204SR5  [R5]
R307  33k  R0204SR5  [R5]
R308  510  R0204SR5  [R5]
R309  8,2k  R0204SR5  [R5]
R310  10  R0207S7,5  [R7,5]
R311  2,7k  R0204SR5  [R5]
R312  47k  R0204SR5  [R5]
R313  22k  R0204SR5  [R5]
R314  100  R0204SR5  [R5]
R315  4,7k  R0204SR5  [R5]
R316  33k  R0207S7,5  [R7,5]
R317  100  R0207S7,5  [R7,5]
R318  33k  R0204SR5  [R5]
R319  2,2  R0204SR5  [R5]
R320  3,9k  R0204SR5  [R5]
R321  0,1  R25X6,5/S  [R27,5]
R322  1k  R0204SR5  [R5]
R323  430  R0204SR5  [R5]
R324  18k  R0204SR5  [R5]
R325  100  R0204SR5  [R5]
R326  33k  R0204SR5  [R5]
R327  510  R0204SR5  [R5]
R328  8,2k  R0204SR5  [R5]
R329  1,2M  R0204LR5  [R5]
R330  1k  R0204SR5  [R5]
R331  47k  R0204SR5  [R5]
R332  22k  R0204SR5  [R5]
R333  1,2M  R0204SR5  [R5]
R334  470k  R0204SR5  [R5]
R407  100k  R0204LR5  [R5]
R408  15k  R0207S7,5  [R7,5]
T2  TYCORT314  [TYCORT314]
T301  5AT  SI520/L  [SICH5*20]
T302  5AT  SI520/L  [SICH5*20]
V301  MJL1302A  MJL1302ALU  [TO-264/LU]
V302  MJL3281A  MJL3281ALU  [TO-264/LU]
V303  MJE15028  MJE15030LU  [TO-220/LU]
V304  BC549C  [TO-92/BC]
V305  2N5401  [TO-92]
V306  2N5551  [TO-92]
V307  BC369  BC640  [SOT-54]
V308  MJE15029  MJE15031LU  [TO-220/LU]
V309  BC559C  [TO-92/BC]
V310  2N3906  [TO-92]
V311  2N5401  [TO-92]
V312  2N5551  [TO-92]
V313  BC549C  [TO-92/BC]
V314  BC549C  [TO-92/BC]
V315  BC546B  BC549C  [TO-92/BC]
V316  BC546B  BC549C  [TO-92/BC]
V317  2N5401  [TO-92]

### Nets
+UB: J3.1 J3.2 T301.1 T301.2 ; also sheet 3
+UB0: C305.1 G301.2(K) G307.1(A) R310.1 T301.3 T301.4 V301.3(E)
+UB2: C304.1 G309.2(K) MP6.1 R301.2 R305.1 R316.1 V304.3(E) ; also sheet 2
-UB: J1.1 J1.2 R334.2 R408.1 T302.1 T302.2 ; also sheet 3
-UB2: C314.2 G314.1(A) MP4.1 R318.2 R321.1 V309.3(E) ; also sheet 2
MASSE: C301.2 C304.2 C305.2 C306.2 C307.2 C308.1 C309.1 C310.1 C311.1 C314.1 C315.2 G308.1(A) G309.1(A) G313.2(K) G314.2(K) G320.1(A) G322.1(A) IC301.2(A) J2.1 J2.2 J305.2 J306.1 MP5.1 R304.2 R311.2 R315.2 R319.1 R324.1 R330.2 T2.11 V313.1(C) V314.3(E) V317.3(C) ; also sheet 1,2,3
N$12: G305.2(K) R309.1 V305.2(B)
N$103: T2.12 ; also sheet 2
N$105: G306.1(A) R310.2
N$106: G305.1(A) R308.2
N$109: C303.2 G308.2(K) R307.1 R309.2 R314.2
N$110: C307.1 R307.2 R315.1 V306.2(B)
N$111: G302.2(K) G303.2(K) R302.1 R303.1 V303.1(B) V304.1(C)
N$112: IC301.3(K) V306.1(E)
N$113: G306.2(K) V301.1(B) V303.2(C)
N$114: G301.1(A) G302.1(A) R301.1 V301.2(C) V303.3(E)
N$115: R303.2 R304.1 V304.2(B)
N$116: G321.2(K) G324.2(K) R333.1 T2.A1(1:A1) V315.1(C)
N$117: C302.2 IC301.1(R) R305.2 R311.1
N$118: C308.2 G310.2(K) G315.1(A) R317.2 T302.3 T302.4 V302.3(E)
N$120: R319.2 V310.1(E)
N$121: G312.1(A) R320.1 V310.2(B) V313.3(E)
N$122: V310.3(C) V311.1(E)
N$123: R320.2 R326.1 V311.2(B)
N$124: C310.2 C312.1 G312.2(K) R316.2 R318.1 V313.2(B)
N$125: R323.1 R324.2 V309.2(B)
N$126: G316.1(A) G317.1(A) R322.2 R323.2 V308.1(B) V309.1(C)
N$127: G315.2(K) G316.2(K) R321.2 V302.2(C) V308.3(E)
N$128: G311.1(A) V302.1(B) V308.2(C)
N$129: R325.1 V312.1(E)
N$130: G319.2(K) R327.1
N$131: G319.1(A) R328.2 V312.2(B)
N$132: C313.1 G313.1(A) R326.2 R328.1
N$133: C301.1 R302.2
N$134: C311.2 R322.1
N$135: C303.1 C306.1 G307.2(K) R306.1 R308.1 R313.1 V307.E
N$136: C309.2 C313.2 G310.1(A) R325.2 R327.2
N$137: G304.2(K) V306.3(C)
N$138: R314.1 V307.C
N$139: R312.1 R313.2 V307.B
N$141: G318.1(A) V311.3(C)
N$177: R312.2 ; also sheet 3
N$180: G324.1(A) R331.1 R332.1 T2.A2(1:A2) V317.1(E)
N$182: C315.1 G323.1(A) J305.1 R407.2
N$183: R329.2 V315.3(E)
N$186: J306.2 R408.2 T2.14
N$200: R330.1 R331.2 V316.3(E)
N$201: G311.2(K) R317.1
N$206: R332.2 V316.1(C) V317.2(B)
N$208: G322.2(K) R329.1 V314.1(C) V316.2(B)
N$210: G320.2(K) G323.2(K) R333.2 R334.1 V314.2(B)
N$211: G321.1(A) V315.2(B) ; also sheet 3
N$230: C302.1 G303.1(A) G304.1(A) V305.3(C)
N$231: C312.2 G317.2(K) G318.2(K) V312.3(C)
N$530: R306.2 V305.1(E)
OFFSET2: R407.1 ; also sheet 2

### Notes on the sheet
- UB0b
- +UB
- MJE15030
- +39V
- GND
- -39V
- MJE15031
- -UB
- +UB0b
- Schutzrelais
- Test
- Aktiv Box
- Endstufe-MHT
- Juni 2009 | Wei | 4

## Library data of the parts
C101 C111 C301 C311 = KOND:M05S2,5/S
C102 C107 C110 C112 C120 C123 C124 C302 C307 C310 C312 C320 C324 = KOND:K5S
C103 C104 C303 C304 = KOND:E3,5S08/S
C105 C106 C108 C109 C305 C306 C308 C309 = KOND:E05S10/S
C113 C115 C313 C315 = KOND:E2,0S05/S
C114 C314 = KOND:E2,5S08/S
C116 C130 C131 C316 C330 C331 = KOND:M05S2,5/L
C117-C119 C126-C128 C317-C319 C326-C328 = KOND:E05S12/L
C121 C321 = KOND:KP5/7/S
C122 C322 = KOND:M05C4,5/S
C125 C325 = KOND:M05C4,5/L
C129 C329 = KOND:M05S4,5/L
C323 = KOND:K5L
G101 G107-G110 G117-G119 G125-G128 G130-G133 G301 G307-G310 G313-G315 G325-G328 G330-G333 = DIODEN:BYV27/S
G102 G112 G113 G115 G136 G137 G302 G303 G312 G316 G317 G335 G337 = DIODEN:1N4148/L
G103-G105 G114 G116 G120-G124 G135 G138 G139 G304 G305 G318-G324 G336 G338 G339 = DIODEN:1N4148/S
G106 G111 G306 G311 = DIODEN:BYV27/L
G129 G134 G329 G334 = DIODEN:BAT41
IC101 IC103 IC104 IC301 IC303 IC304 = ICS35:TL431
IC102 IC302 = ICS35:LM6361N
IC105 IC305 = ICS35:LF353
J1-J3 J101-J104 J301-J304 = STECKER:FLACH6,3
J4 J106 J306 = STECKER:BERG02SW
J105 J305 = STECKER:JUMP/O/S
J107 J307 = STECKER:SMBR665
MP1-MP3 MP7-MP12 MP15 MP16 = VERSCH35:MESS-R/S
MP4-MP6 MP13 MP14 = VERSCH35:MESS-R/L
P101 P301 = WID:POT6,7/S
R101 R119 R301 R321 = WID:R25X6,5/S
R102-R109 R111-R115 R118 R120-R132 R134 R152 R154 R155 R157-R159 R161 R164-R167 R171 R176 R177 R179-R184 R302-R309 R311-R315 R318-R320 R322-R328 R330-R334 R352 R353 R355 R356 R358 R359 R361 R364-R367 R371 R376 R377 R379-R384 = WID:R0204S
R110 R116 R117 R145 R146 R148-R150 R156 R174 R196 R198 R199 R205 R206 R208 R310 R316 R317 R345 R346 R348-R350 R357 R374 R396 R398 R399 R405 R406 R408 = WID:R0207S
R133 R147 R153 R160 R168-R170 R172 R173 R178 R185 R197 R200-R204 R207 R329 R347 R354 R360 R368-R370 R372 R373 R378 R385 R397 R400-R404 R407 = WID:R0204L
R135-R144 R151 R175 R186-R195 R335-R344 R351 R375 R386-R395 = WID:R0207L
R162 R163 R362 R363 = WID:NTC5,0/S
T1 T2 = RELAIS:TYCORT314
T101 T102 T301 T302 = VERSCH35:SI5*20/L
U$200 = VERSCH35:LÖTFA
V101 V301 = TRANS:MJL1302A
V102 V302 = TRANS:MJL3281A
V103 V119 V133 V303 V319 V333 = TRANS:MJE15030
V104 V113 V114 V304 V313-V316 = TRANS:BC549C
V105 V111 V117 V130 V305 V311 V317 V330 = TRANS:2N5401
V106 V112 V125 V306 V312 V325 = TRANS:2N5551
V107 V307 = TRANS:BC640
V108 V120 V132 V308 V320 V332 = TRANS:MJE15031
V109 V309 = TRANS:BC559C
V110 V310 = TRANS:2N3906
V115 V116 = TRANS:BC547C
V118 V318 = TRANS:2SA1215S
V121 V123 V127 V321 V323 V327 = TRANS:BD140
V122 V126 V128 V322 V326 V328 = TRANS:BD139
V124 V324 = SMDREFLO:BCV62
V129 V329 = SMDREFLO:BCV61
V131 V331 = TRANS:2SC2921S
